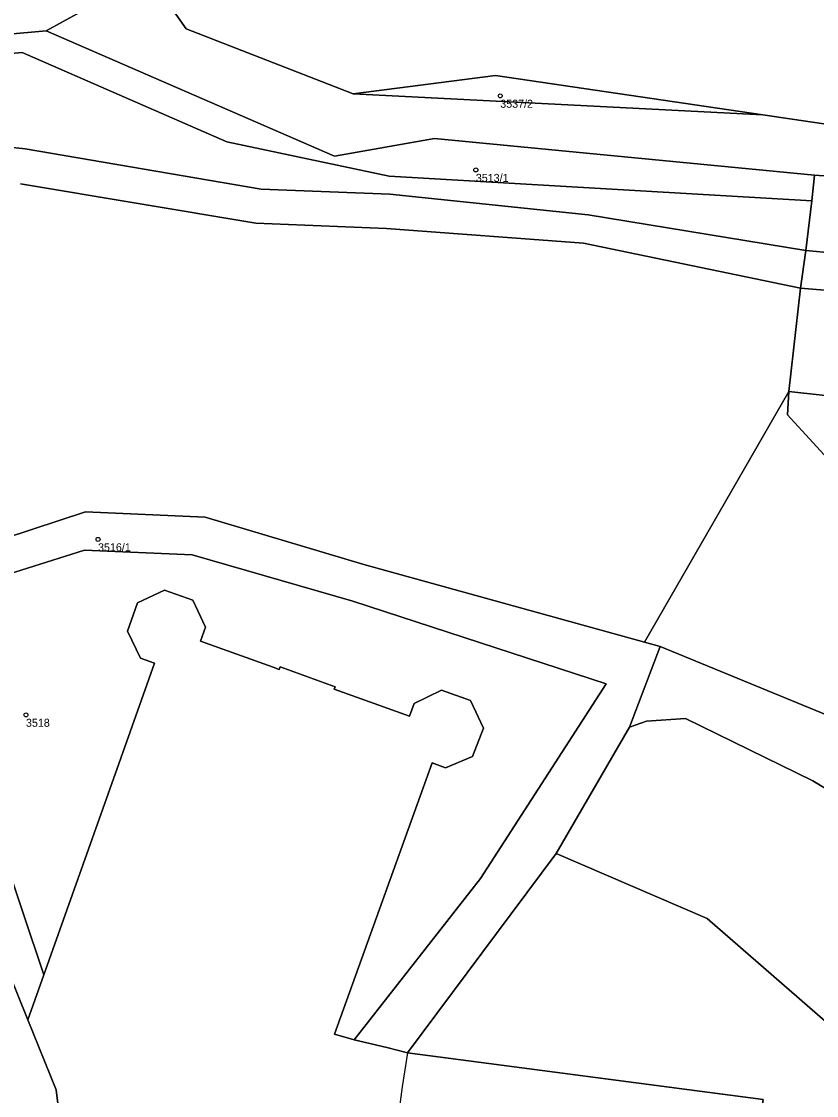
# Model space of a CAD drawing. Extents: x -878211 to -870363, y -1058464 to -1052522.
# Drawn here: x -876444.5 to -876345.2, y -1055057.5 to -1054923.3 of the extents above; entities that cross this region are included whole.
import ezdxf

# ---------------------------------------------------------------- set-up
doc = ezdxf.new("R2010")
doc.units = 0
for name, color, linetype in [('Vrstva 50', 7, 'Continuous'), ('Vrstva 51', 7, 'Continuous'), ('Vrstva 52', 7, 'Continuous')]:
    doc.layers.add(name, color=color, linetype=linetype)

msp = doc.modelspace()

# ---------------------------------------------------------------- linework, layer by layer
at = {"layer": 'Vrstva 50'}
for centre in [(-876384.73, -1054932.59994), (-876387.78, -1054941.85994), (-876434.97, -1054988.00994), (-876443.97, -1055009.92994)]:
    msp.add_circle(centre, 0.25, dxfattribs=at)
at = {"layer": 'Vrstva 51'}
for points in [[(-876554.58, -1054918.01), (-876531.66, -1054936.08), (-876520.3, -1054937.9), (-876510.58, -1054933.13), (-876503.33, -1054929.57), (-876490.9, -1054928.94), (-876441.45, -1054924.49), (-876428.71, -1054917.43), (-876427.47, -1054915.93), (-876423.48, -1054914.13), (-876418.87, -1054910.9), (-876408.73, -1054905.38), (-876399.9, -1054901.85), (-876380.69, -1054897.58), (-876356, -1054887.75), (-876339.28, -1054874.2), (-876318.21, -1054867.84), (-876309.04, -1054869.25), (-876299.88, -1054875.09), (-876297.96, -1054890.06), (-876291.78, -1054906.9), (-876262.86, -1054909.66), (-876243.34, -1054905.33)], [(-876325.98, -1054938.79), (-876351.91, -1054934.98), (-876403.1, -1054932.35), (-876423.95, -1054924.24), (-876428.71, -1054917.43), (-876441.45, -1054924.49), (-876405.43, -1054940.12), (-876392.93, -1054937.94), (-876345.46, -1054942.49), (-876321.14, -1054944.23)], [(-876444.66, -1054943.59), (-876415.24, -1054948.5), (-876398.94, -1054949.17), (-876374.34, -1054951.01), (-876347.21, -1054956.62), (-876346.55, -1054951.9), (-876373.73, -1054947.48), (-876398.52, -1054944.88), (-876414.59, -1054944.25), (-876444.08, -1054939.2), (-876457.23, -1054937.79)], [(-876449.98, -1054989), (-876436.53, -1054984.57), (-876421.59, -1054985.25), (-876401.77, -1054991.15), (-876366.72, -1055000.87), (-876348.7, -1054969.52), (-876347.21, -1054956.62), (-876374.34, -1054951.01), (-876398.94, -1054949.17), (-876415.24, -1054948.5), (-876444.66, -1054943.59)], [(-876247.95, -1054964.03), (-876267.26, -1054960.95), (-876296.49, -1054956.28), (-876299.2, -1054956.16), (-876307.13, -1054955.82), (-876321.8, -1054954.26), (-876346.55, -1054951.9), (-876347.21, -1054956.62), (-876322.54, -1054958.67), (-876301.81, -1054960.98), (-876293.7, -1054961.9), (-876291.01, -1054962.38), (-876285.26, -1054964.19), (-876245.2, -1054971.07)], [(-876448.56, -1054993.12), (-876436.65, -1054989.35), (-876423.21, -1054989.96), (-876403.14, -1054995.71), (-876371.51, -1055006.07), (-876387.2, -1055030.38), (-876402.97, -1055050.51), (-876398.88, -1055051.49), (-876396.33, -1055052.17), (-876377.75, -1055027.25), (-876368.57, -1055011.46), (-876364.74, -1055001.39), (-876366.72, -1055000.87), (-876401.77, -1054991.15), (-876421.59, -1054985.25), (-876436.53, -1054984.57), (-876449.98, -1054989)], [(-876446.93, -1055026.87), (-876441.73, -1055042.41), (-876432.59, -1055016.65), (-876427.91, -1055003.46), (-876429.67, -1055002.83), (-876431.27, -1054999.47), (-876430.02, -1054995.95), (-876426.66, -1054994.35), (-876423.14, -1054995.6), (-876421.54, -1054998.96), (-876422.16, -1055000.72), (-876413.09, -1055003.99), (-876412.35, -1055004.25), (-876412.23, -1055003.93), (-876405.36, -1055006.41), (-876405.46, -1055006.72), (-876396.05, -1055010.1), (-876395.47, -1055008.52), (-876392.05, -1055006.84), (-876388.43, -1055008.13), (-876386.81, -1055011.59), (-876388.2, -1055015.14), (-876391.56, -1055016.55), (-876393.22, -1055015.91), (-876405.45, -1055049.81), (-876402.97, -1055050.51), (-876387.2, -1055030.38), (-876371.51, -1055006.07), (-876403.14, -1054995.71), (-876423.21, -1054989.96), (-876436.65, -1054989.35), (-876448.56, -1054993.12)], [(-876351.9, -1055057.99), (-876396.33, -1055052.17), (-876398.88, -1055051.49), (-876402.97, -1055050.51), (-876405.45, -1055049.81), (-876393.22, -1055015.91), (-876391.56, -1055016.55), (-876388.2, -1055015.14), (-876386.81, -1055011.59), (-876388.43, -1055008.13), (-876392.05, -1055006.84), (-876395.47, -1055008.52), (-876396.05, -1055010.1), (-876405.46, -1055006.72), (-876405.36, -1055006.41), (-876412.23, -1055003.93), (-876412.35, -1055004.25), (-876413.09, -1055003.99), (-876422.16, -1055000.72), (-876421.54, -1054998.96), (-876423.14, -1054995.6), (-876426.66, -1054994.35), (-876430.02, -1054995.95), (-876431.27, -1054999.47), (-876429.67, -1055002.83), (-876427.91, -1055003.46), (-876432.59, -1055016.65), (-876441.73, -1055042.41), (-876443.73, -1055048.04), (-876440.19, -1055056.77), (-876439.91, -1055059.13)], [(-876319.98, -1055019.81), (-876364.74, -1055001.39), (-876368.57, -1055011.46), (-876366.45, -1055010.72), (-876361.59, -1055010.4), (-876345.67, -1055018.17), (-876326.07, -1055030.03)], [(-876236.43, -1055051), (-876251.86, -1055052.34), (-876270.53, -1055053.27), (-876283.55, -1055052.17), (-876286.3, -1055051.17), (-876307.7, -1055040.24), (-876326.07, -1055030.03), (-876345.67, -1055018.17), (-876361.59, -1055010.4), (-876366.45, -1055010.72), (-876368.57, -1055011.46), (-876377.75, -1055027.25), (-876358.9, -1055035.38), (-876323.34, -1055066.32), (-876306.38, -1055081.71), (-876316.66, -1055102.83), (-876314.44, -1055103.64), (-876294.05, -1055111.65), (-876279.48, -1055115.89), (-876264.87, -1055113.38), (-876253.17, -1055110.11), (-876221.24, -1055096.79)], [(-876451.62, -1055028.58), (-876443.73, -1055048.04), (-876441.73, -1055042.41), (-876446.93, -1055026.87)], [(-876439.91, -1055059.13), (-876440.19, -1055056.77), (-876443.73, -1055048.04), (-876451.62, -1055028.58)]]:
    msp.add_lwpolyline(points, dxfattribs=at)
for points in [[(-876385.33, -1054930.06), (-876351.91, -1054934.98), (-876325.98, -1054938.79), (-876302.79, -1054937.47), (-876294.48, -1054932.58), (-876286.97, -1054928.17), (-876291.78, -1054906.9), (-876297.96, -1054890.06), (-876299.88, -1054875.09), (-876309.04, -1054869.25), (-876318.21, -1054867.84), (-876339.28, -1054874.2), (-876356, -1054887.75), (-876380.69, -1054897.58), (-876399.9, -1054901.85), (-876408.73, -1054905.38), (-876418.87, -1054910.9), (-876423.48, -1054914.13), (-876427.47, -1054915.93), (-876428.71, -1054917.43), (-876423.95, -1054924.24), (-876403.1, -1054932.35)], [(-876392.93, -1054937.94), (-876405.43, -1054940.12), (-876441.45, -1054924.49), (-876490.9, -1054928.94), (-876503.33, -1054929.57), (-876510.58, -1054933.13), (-876444.45, -1054927.2), (-876418.9, -1054938.34), (-876398.61, -1054942.65), (-876345.83, -1054945.71), (-876345.46, -1054942.49)], [(-876501.47, -1054948.15), (-876491.88, -1054942.07), (-876476.52, -1054938.14), (-876457.23, -1054937.79), (-876444.08, -1054939.2), (-876414.59, -1054944.25), (-876398.52, -1054944.88), (-876373.73, -1054947.48), (-876346.55, -1054951.9), (-876345.83, -1054945.71), (-876398.61, -1054942.65), (-876418.9, -1054938.34), (-876444.45, -1054927.2), (-876510.58, -1054933.13), (-876520.3, -1054937.9), (-876531.66, -1054936.08), (-876526.09, -1054970.36), (-876515.19, -1055001.33), (-876513.45, -1054983.48), (-876509.73, -1054969.43), (-876507.69, -1054958.58)], [(-876385.33, -1054930.06), (-876403.1, -1054932.35), (-876351.91, -1054934.98)], [(-876321.8, -1054954.26), (-876321.14, -1054944.23), (-876345.46, -1054942.49), (-876345.83, -1054945.71), (-876346.55, -1054951.9)], [(-876323.7, -1054972.29), (-876322.54, -1054958.67), (-876347.21, -1054956.62), (-876348.7, -1054969.52)], [(-876348.7, -1054969.52), (-876366.72, -1055000.87), (-876364.74, -1055001.39), (-876319.98, -1055019.81), (-876319.3, -1055020.38), (-876313.33, -1055013.57), (-876312.3, -1055000.03), (-876311.19, -1054997.97), (-876326.11, -1054997.28), (-876348.87, -1054972.47)], [(-876323.78, -1054973.29), (-876323.7, -1054972.29), (-876348.7, -1054969.52), (-876348.87, -1054972.47), (-876326.11, -1054997.28), (-876311.19, -1054997.97), (-876307.31, -1054994.01), (-876325.75, -1054993.15)], [(-876316.66, -1055102.83), (-876306.38, -1055081.71), (-876323.34, -1055066.32), (-876358.9, -1055035.38), (-876377.75, -1055027.25), (-876396.33, -1055052.17), (-876351.9, -1055057.99), (-876356.57, -1055092.43), (-876334.52, -1055096.3)]]:
    msp.add_lwpolyline(points, close=True, dxfattribs=at)
at = {"layer": 'Vrstva 52'}
msp.add_lwpolyline([(-876401.03, -1055086.59), (-876356.57, -1055092.43), (-876351.9, -1055057.99), (-876396.33, -1055052.17), (-876396.96, -1055056.38)], close=True, dxfattribs=at)

# ---------------------------------------------------------------- texts
at = {"layer": 'Vrstva 50'}
for s, p in [('3537/2', (-876384.73, -1054934.089)), ('3513/1', (-876387.78, -1054943.349)), ('3516/1', (-876434.97, -1054989.499)), ('3518', (-876443.97, -1055011.419))]:
    msp.add_text(s, height=0.999996, dxfattribs=at).set_placement(p)

doc.saveas('drawing.dxf')
